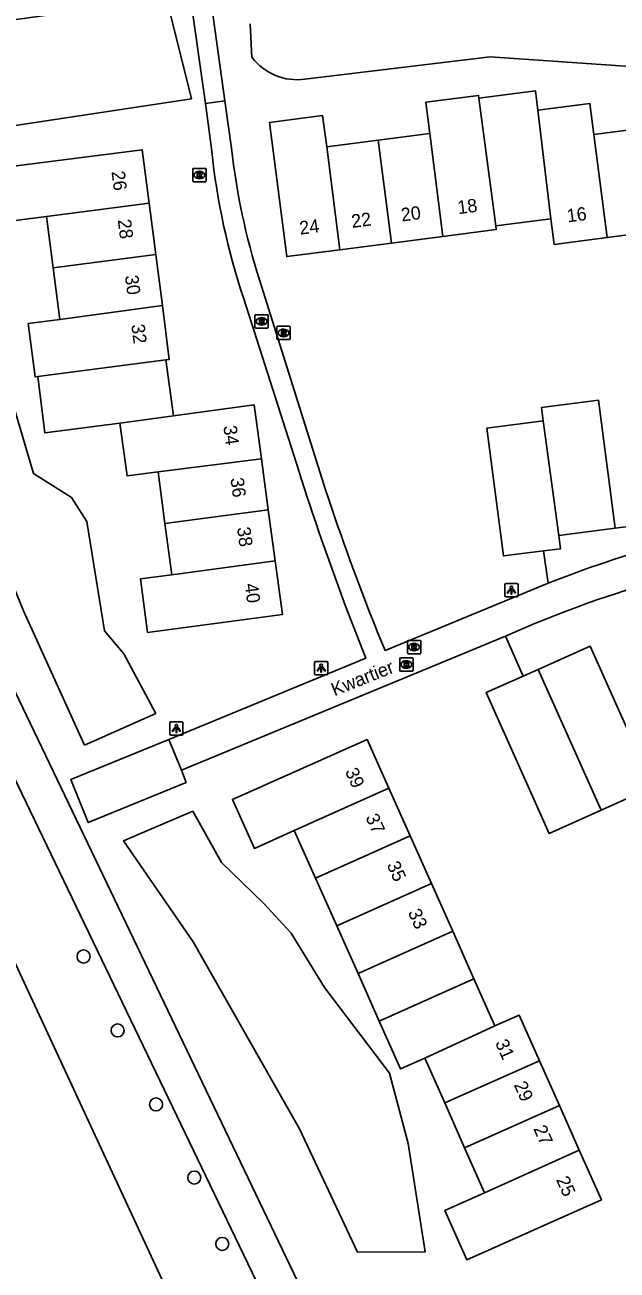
# Model space of a CAD drawing. Extents: x 159451 to 160663, y 388402 to 389723.
# Drawn here: x 159511.2 to 159555.6, y 389199.9 to 389293.3 of the extents above; entities that cross this region are included whole.
import ezdxf

# ---------------------------------------------------------------- set-up
doc = ezdxf.new("R2010")
doc.units = 0
for name, color, linetype in [('IMGEO_Boom', 7, 'Continuous'), ('IMGEO_Bouwland', 7, 'Continuous'), ('IMGEO_Grasland_overig', 7, 'Continuous'), ('IMGEO_Lichtpunt', 7, 'Continuous'), ('IMGEO_Meer_plas_ven_vijver', 7, 'Continuous'), ('IMGEO_Openbare_ruimte_label', 7, 'Continuous'), ('IMGEO_Pand', 7, 'Continuous'), ('IMGEO_Pand_nummerreeks', 7, 'Continuous'), ('IMGEO_Rijbaan_lokaal_gesloten', 7, 'Continuous'), ('IMGEO_Rijbaan_lokaal_halfverhard', 7, 'Continuous'), ('IMGEO_Rioolput', 7, 'Continuous')]:
    doc.layers.add(name, color=color, linetype=linetype)

msp = doc.modelspace()

# ---------------------------------------------------------------- linework, layer by layer
at = {"layer": 'IMGEO_Boom'}
for centre in [(159515.645, 389223.44), (159518.196, 389217.898), (159521.076, 389212.352), (159523.945, 389206.87), (159526.044, 389201.9)]:
    msp.add_circle(centre, 0.489, dxfattribs=at)
at = {"layer": 'IMGEO_Bouwland'}
msp.add_lwpolyline([(159539.156, 389122.203), (159538.081, 389141.023), (159537.243, 389155.693), (159534.303, 389168.702), (159530.224, 389180.456), (159487.441, 389272.575)], dxfattribs=at)
at = {"layer": 'IMGEO_Grasland_overig'}
for points in [[(159552.375, 389144.269), (159550.196, 389160.656), (159546.355, 389164.126), (159540.689, 389183.824), (159539.945, 389186.409), (159538.67, 389189.107), (159536.847, 389188.304), (159486.712, 389292.863)], [(159493.1, 389273.212), (159500, 389258.58), (159504.093, 389250), (159534.245, 389187.399), (159541.062, 389164.374)]]:
    msp.add_lwpolyline(points, dxfattribs=at)
at = {"layer": 'IMGEO_Lichtpunt'}
for p, q in [((159547.227, 389251.307), (159547.227, 389250.5)), ((159547.227, 389251.307), (159547.227, 389250.5)), ((159548.129, 389251.402), (159547.321, 389251.402)), ((159548.129, 389251.402), (159547.321, 389251.402)), ((159548.223, 389250.5), (159548.223, 389251.307)), ((159548.223, 389250.5), (159548.223, 389251.307)), ((159547.321, 389250.406), (159548.129, 389250.406)), ((159547.321, 389250.406), (159548.129, 389250.406)), ((159532.965, 389245.462), (159532.965, 389244.655)), ((159532.965, 389245.462), (159532.965, 389244.655)), ((159533.867, 389245.557), (159533.059, 389245.557)), ((159533.867, 389245.557), (159533.059, 389245.557)), ((159533.961, 389244.655), (159533.961, 389245.462)), ((159533.961, 389244.655), (159533.961, 389245.462)), ((159533.059, 389244.561), (159533.867, 389244.561)), ((159533.059, 389244.561), (159533.867, 389244.561)), ((159522.102, 389240.935), (159522.102, 389240.128)), ((159522.102, 389240.935), (159522.102, 389240.128)), ((159523.004, 389241.03), (159522.196, 389241.03)), ((159523.004, 389241.03), (159522.196, 389241.03)), ((159523.098, 389240.128), (159523.098, 389240.935)), ((159523.098, 389240.128), (159523.098, 389240.935)), ((159522.196, 389240.034), (159523.004, 389240.034)), ((159522.196, 389240.034), (159523.004, 389240.034))]:
    msp.add_line(p, q, dxfattribs=at)
for points in [[(159547.601, 389250.971), (159547.64, 389250.943), (159547.452, 389250.681), (159547.414, 389250.708), (159547.601, 389250.971)], [(159547.703, 389250.923), (159547.75, 389250.923), (159547.75, 389250.601), (159547.703, 389250.601), (159547.703, 389250.923)], [(159547.813, 389250.943), (159547.851, 389250.97), (159548.038, 389250.708), (159547.999, 389250.68), (159547.813, 389250.943)], [(159533.339, 389245.126), (159533.378, 389245.098), (159533.19, 389244.836), (159533.152, 389244.863), (159533.339, 389245.126)], [(159533.441, 389245.078), (159533.488, 389245.078), (159533.488, 389244.756), (159533.441, 389244.756), (159533.441, 389245.078)], [(159533.551, 389245.098), (159533.589, 389245.125), (159533.776, 389244.863), (159533.737, 389244.835), (159533.551, 389245.098)], [(159522.476, 389240.599), (159522.515, 389240.571), (159522.327, 389240.309), (159522.289, 389240.336), (159522.476, 389240.599)], [(159522.578, 389240.551), (159522.625, 389240.551), (159522.625, 389240.229), (159522.578, 389240.229), (159522.578, 389240.551)], [(159522.688, 389240.571), (159522.726, 389240.598), (159522.913, 389240.336), (159522.874, 389240.308), (159522.688, 389240.571)]]:
    msp.add_lwpolyline(points, dxfattribs=at)
for centre in [(159547.726, 389251.105), (159533.464, 389245.26), (159522.601, 389240.733)]:
    msp.add_circle(centre, 0.0994, dxfattribs=at)
for centre, start, end in [((159547.321, 389251.307), 90, 180), ((159547.321, 389251.307), 90, 180), ((159548.129, 389251.307), 0, 90), ((159548.129, 389251.307), 0, 90), ((159547.321, 389250.5), 180, 270), ((159547.321, 389250.5), 180, 270), ((159548.129, 389250.5), 270, 0), ((159548.129, 389250.5), 270, 360), ((159533.059, 389245.462), 90, 180), ((159533.059, 389245.462), 90, 180), ((159533.867, 389245.462), 0, 90), ((159533.867, 389245.462), 0, 90), ((159533.059, 389244.655), 180, 270), ((159533.059, 389244.655), 180, 270), ((159533.867, 389244.655), 270, 0), ((159533.867, 389244.655), 270, 360), ((159522.196, 389240.935), 90, 180), ((159522.196, 389240.935), 90, 180), ((159523.004, 389240.935), 0, 90), ((159523.004, 389240.935), 0, 90), ((159522.196, 389240.128), 180, 270), ((159522.196, 389240.128), 180, 270), ((159523.004, 389240.128), 270, 0), ((159523.004, 389240.128), 270, 360)]:
    msp.add_arc(centre, 0.0946, start, end, dxfattribs=at)
at = {"layer": 'IMGEO_Meer_plas_ven_vijver'}
for points in [[(159521.069, 389241.65), (159518.659, 389246.126), (159517.22, 389247.851), (159515.886, 389256.055), (159514.744, 389257.84), (159511.894, 389259.653), (159504.61, 389284.226), (159509.011, 389285.515), (159523.74, 389287.733), (159521.85, 389295.267), (159496.278, 389291.663), (159494.831, 389290.177), (159494.743, 389289.39), (159511.127, 389249.352), (159515.724, 389239.283), (159521.069, 389241.65)], [(159528.272, 389290.814), (159528.13, 389293.352)], [(159556.966, 389290.126), (159546.129, 389290.863), (159532.239, 389289.197)], [(159523.847, 389234.341), (159518.626, 389232.107), (159523.869, 389224.551), (159531.83, 389210.522), (159536.188, 389201.27), (159541.252, 389201.297), (159539.985, 389209.42), (159538.578, 389214.693), (159533.719, 389221.109), (159531.217, 389225.185), (159529.13, 389227.44), (159525.975, 389230.482), (159523.847, 389234.341)]]:
    msp.add_lwpolyline(points, dxfattribs=at)
msp.add_arc((159531.661, 389293.453), 4.295, 217.90944, 277.73769, dxfattribs=at)
at = {"layer": 'IMGEO_Pand'}
for points in [[(159541.594, 389285.127), (159541.295, 389287.473), (159545.256, 389287.981), (159545.281, 389287.787)], [(159545.281, 389287.787), (159549.518, 389288.329), (159549.707, 389286.878)], [(159546.558, 389278.199), (159545.281, 389287.787)], [(159549.707, 389286.878), (159553.612, 389287.385), (159553.913, 389285.047)], [(159549.707, 389286.878), (159550.68, 389278.733)], [(159534.868, 389276.415), (159530.881, 389275.898), (159529.576, 389285.954), (159533.569, 389286.469), (159533.872, 389284.123)], [(159537.733, 389284.625), (159541.594, 389285.127)], [(159542.577, 389277.414), (159541.594, 389285.127)], [(159553.913, 389285.047), (159557.776, 389285.546)], [(159553.913, 389285.047), (159554.906, 389277.332)], [(159520.557, 389279.914), (159520.041, 389283.908), (159510.008, 389282.625), (159510.521, 389278.616), (159512.856, 389278.918)], [(159533.872, 389284.123), (159537.733, 389284.625)], [(159534.868, 389276.415), (159533.872, 389284.123)], [(159538.735, 389276.916), (159537.733, 389284.625)], [(159520.557, 389279.914), (159512.856, 389278.918)], [(159521.057, 389276.054), (159520.557, 389279.914)], [(159512.856, 389278.918), (159513.355, 389275.058)], [(159546.558, 389278.199), (159546.592, 389277.935), (159542.577, 389277.414)], [(159550.68, 389278.733), (159546.558, 389278.199)], [(159554.906, 389277.332), (159550.926, 389276.815), (159550.68, 389278.733)], [(159542.577, 389277.414), (159538.735, 389276.916)], [(159558.771, 389277.834), (159554.906, 389277.332)], [(159538.735, 389276.916), (159534.868, 389276.415)], [(159513.355, 389275.058), (159521.057, 389276.054)], [(159521.551, 389272.231), (159521.057, 389276.054)], [(159513.355, 389275.058), (159513.854, 389271.198)], [(159521.551, 389272.231), (159513.854, 389271.198)], [(159521.819, 389268.158), (159522.073, 389268.192), (159521.551, 389272.231)], [(159513.854, 389271.198), (159511.491, 389270.881), (159512.009, 389266.885), (159512.202, 389266.91)], [(159512.202, 389266.91), (159521.819, 389268.158)], [(159521.819, 389268.158), (159522.384, 389263.975)], [(159518.374, 389263.415), (159512.749, 389262.686), (159512.202, 389266.91)], [(159550.103, 389263.588), (159549.974, 389264.586), (159554.246, 389265.142), (159555.492, 389255.556)], [(159528.974, 389260.743), (159528.428, 389264.791), (159522.384, 389263.975)], [(159522.384, 389263.975), (159518.374, 389263.415)], [(159518.374, 389263.415), (159518.902, 389259.462), (159521.237, 389259.759)], [(159550.103, 389263.588), (159545.873, 389263.038), (159547.128, 389253.464), (159550.122, 389253.843)], [(159551.271, 389255.006), (159550.103, 389263.588)], [(159528.974, 389260.743), (159521.237, 389259.759)], [(159529.489, 389256.929), (159528.974, 389260.743)], [(159521.237, 389259.759), (159521.746, 389255.905)], [(159529.489, 389256.929), (159521.746, 389255.905)], [(159530.008, 389253.087), (159529.489, 389256.929)], [(159521.746, 389255.905), (159522.256, 389252.051)], [(159550.122, 389253.843), (159551.405, 389254.005), (159551.271, 389255.006)], [(159555.492, 389255.556), (159551.271, 389255.006)], [(159522.256, 389252.051), (159519.913, 389251.738), (159520.446, 389247.737), (159530.55, 389249.068), (159530.008, 389253.087)], [(159522.256, 389252.051), (159530.008, 389253.087)], [(159549.724, 389244.959), (159553.631, 389246.699), (159557.562, 389237.923)], [(159548.614, 389244.465), (159549.724, 389244.959)], [(159554.447, 389234.413), (159549.724, 389244.959)], [(159548.614, 389244.465), (159545.842, 389243.23), (159550.543, 389232.664), (159554.447, 389234.413)], [(159531.434, 389232.875), (159528.453, 389231.539), (159526.807, 389235.21), (159536.903, 389239.704), (159538.532, 389236.056)], [(159554.447, 389234.413), (159558.351, 389236.161), (159557.562, 389237.923)], [(159538.532, 389236.056), (159531.434, 389232.875)], [(159538.532, 389236.056), (159540.13, 389232.476)], [(159533.03, 389229.303), (159531.434, 389232.875)], [(159540.13, 389232.476), (159533.03, 389229.303)], [(159540.13, 389232.476), (159541.724, 389228.904)], [(159534.626, 389225.732), (159533.03, 389229.303)], [(159534.626, 389225.732), (159541.724, 389228.904)], [(159541.724, 389228.904), (159543.319, 389225.331)], [(159536.221, 389222.16), (159534.626, 389225.732)], [(159543.319, 389225.331), (159536.221, 389222.16)], [(159543.319, 389225.331), (159544.914, 389221.759)], [(159537.817, 389218.589), (159536.221, 389222.16)], [(159537.817, 389218.589), (159544.914, 389221.759)], [(159544.914, 389221.759), (159546.482, 389218.246)], [(159541.221, 389215.825), (159539.413, 389215.017), (159537.817, 389218.589)], [(159546.482, 389218.246), (159548.293, 389219.053), (159549.821, 389215.625)], [(159546.482, 389218.246), (159541.221, 389215.825)], [(159542.719, 389212.462), (159541.221, 389215.825)], [(159542.719, 389212.462), (159549.821, 389215.625)], [(159549.821, 389215.625), (159551.319, 389212.262)], [(159544.217, 389209.098), (159542.719, 389212.462)], [(159544.217, 389209.098), (159551.319, 389212.262)], [(159551.319, 389212.262), (159552.806, 389208.926)], [(159545.715, 389205.735), (159544.217, 389209.098)], [(159552.806, 389208.926), (159554.466, 389205.201), (159544.38, 389200.71), (159542.733, 389204.393), (159545.715, 389205.735)], [(159545.715, 389205.735), (159552.806, 389208.926)]]:
    msp.add_lwpolyline(points, dxfattribs=at)
at = {"layer": 'IMGEO_Rijbaan_lokaal_gesloten'}
for points in [[(159523.669, 389295.299), (159524.796, 389287.372)], [(159526.226, 389287.573), (159525.136, 389295.518)], [(159524.796, 389287.372), (159526.226, 389287.573)], [(159526.723, 389284.029), (159526.226, 389287.573)], [(159524.796, 389287.372), (159525.256, 389283.811)], [(159533.776, 389258.43), (159528.825, 389274.169)], [(159527.637, 389272.799), (159531.804, 389259.756)], [(159550.467, 389251.425), (159538.251, 389246.377), (159537.657, 389247.809)], [(159535.285, 389249.699), (159536.816, 389245.805), (159522.027, 389239.718)], [(159522.997, 389237.416), (159547.283, 389247.447)], [(159522.027, 389239.718), (159514.682, 389236.714), (159515.988, 389233.475), (159523.334, 389236.494), (159522.997, 389237.416)], [(159522.997, 389237.416), (159522.027, 389239.718)]]:
    msp.add_lwpolyline(points, dxfattribs=at)
for centre, radius, start, end in [((159576.84, 389289.201), 51.865, 185.96525, 198.43596), ((159579.613, 389290.15), 53.243, 186.60177, 197.46708), ((159748.156, 389329.01), 227.166, 197.74989, 200.43436), ((159718.88, 389320.049), 195.091, 198.41199, 201.73344), ((159584.912, 389163.233), 94.68, 105.81014, 111.33379), ((159582.261, 389169.306), 85.612, 105.35087, 114.11468)]:
    msp.add_arc(centre, radius, start, end, dxfattribs=at)
at = {"layer": 'IMGEO_Rijbaan_lokaal_halfverhard'}
for points in [[(159555.492, 389255.556), (159558.754, 389255.947), (159559.116, 389254.331)], [(159550.467, 389251.425), (159550.122, 389253.843)], [(159547.283, 389247.447), (159548.614, 389244.465)]]:
    msp.add_lwpolyline(points, dxfattribs=at)
at = {"layer": 'IMGEO_Rioolput'}
for p, q in [((159523.83, 389281.589), (159523.83, 389282.441)), ((159523.905, 389282.515), (159524.757, 389282.515)), ((159524.318, 389282.295), (159524.343, 389282.295)), ((159524.831, 389282.441), (159524.831, 389281.589)), ((159524.757, 389281.515), (159523.905, 389281.515)), ((159524.341, 389281.735), (159524.316, 389281.735)), ((159528.494, 389270.621), (159528.494, 389271.473)), ((159528.569, 389271.547), (159529.421, 389271.547)), ((159529.005, 389270.767), (159528.98, 389270.767)), ((159528.982, 389271.327), (159529.007, 389271.327)), ((159529.495, 389271.473), (159529.495, 389270.621)), ((159530.212, 389270.679), (159531.064, 389270.679)), ((159529.421, 389270.547), (159528.569, 389270.547)), ((159530.137, 389269.753), (159530.137, 389270.605)), ((159530.648, 389269.899), (159530.623, 389269.899)), ((159530.625, 389270.459), (159530.65, 389270.459)), ((159531.138, 389270.605), (159531.138, 389269.753)), ((159531.064, 389269.679), (159530.212, 389269.679)), ((159539.923, 389246.21), (159539.923, 389247.062)), ((159539.998, 389247.136), (159540.85, 389247.136)), ((159540.411, 389246.916), (159540.436, 389246.916)), ((159540.924, 389247.062), (159540.924, 389246.21)), ((159539.345, 389244.902), (159539.345, 389245.754)), ((159539.42, 389245.828), (159540.272, 389245.828)), ((159539.833, 389245.608), (159539.858, 389245.608)), ((159540.85, 389246.136), (159539.998, 389246.136)), ((159540.346, 389245.754), (159540.346, 389244.902)), ((159540.434, 389246.356), (159540.409, 389246.356)), ((159540.272, 389244.828), (159539.42, 389244.828)), ((159539.856, 389245.048), (159539.831, 389245.048))]:
    msp.add_line(p, q, dxfattribs=at)
for points in [[(159523.83, 389281.589), (159523.83, 389282.441)], [(159523.905, 389282.515), (159524.757, 389282.515)], [(159524.419, 389282.213), (159524.167, 389282.215), (159524.167, 389281.815)], [(159524.167, 389281.815), (159524.291, 389281.815), (159524.291, 389281.977), (159524.302, 389281.977)], [(159524.345, 389282.134), (159524.291, 389282.134), (159524.291, 389282.053)], [(159524.291, 389282.053), (159524.343, 389282.053)], [(159524.349, 389281.948), (159524.42, 389281.815), (159524.56, 389281.815), (159524.495, 389281.941)], [(159524.831, 389282.441), (159524.831, 389281.589)], [(159524.757, 389281.515), (159523.905, 389281.515)], [(159528.494, 389270.621), (159528.494, 389271.473)], [(159528.569, 389271.547), (159529.421, 389271.547)], [(159529.083, 389271.245), (159528.831, 389271.247), (159528.831, 389270.847)], [(159528.831, 389270.847), (159528.955, 389270.847), (159528.955, 389271.009), (159528.966, 389271.009)], [(159529.009, 389271.166), (159528.955, 389271.166), (159528.955, 389271.085)], [(159528.955, 389271.085), (159529.007, 389271.085)], [(159529.013, 389270.98), (159529.084, 389270.847), (159529.224, 389270.847), (159529.159, 389270.973)], [(159529.495, 389271.473), (159529.495, 389270.621)], [(159530.212, 389270.679), (159531.064, 389270.679)], [(159529.421, 389270.547), (159528.569, 389270.547)], [(159530.137, 389269.753), (159530.137, 389270.605)], [(159530.726, 389270.377), (159530.474, 389270.379), (159530.474, 389269.979)], [(159530.474, 389269.979), (159530.598, 389269.979), (159530.598, 389270.141), (159530.609, 389270.141)], [(159530.652, 389270.298), (159530.598, 389270.298), (159530.598, 389270.217)], [(159530.598, 389270.217), (159530.65, 389270.217)], [(159530.656, 389270.112), (159530.727, 389269.979), (159530.867, 389269.979), (159530.802, 389270.105)], [(159531.138, 389270.605), (159531.138, 389269.753)], [(159531.064, 389269.679), (159530.212, 389269.679)], [(159539.923, 389246.21), (159539.923, 389247.062)], [(159539.998, 389247.136), (159540.85, 389247.136)], [(159540.512, 389246.834), (159540.26, 389246.836), (159540.26, 389246.436)], [(159540.26, 389246.436), (159540.384, 389246.436), (159540.384, 389246.598), (159540.395, 389246.598)], [(159540.438, 389246.755), (159540.384, 389246.755), (159540.384, 389246.674)], [(159540.384, 389246.674), (159540.436, 389246.674)], [(159540.442, 389246.569), (159540.513, 389246.436), (159540.653, 389246.436), (159540.588, 389246.562)], [(159540.924, 389247.062), (159540.924, 389246.21)], [(159539.345, 389244.902), (159539.345, 389245.754)], [(159539.42, 389245.828), (159540.272, 389245.828)], [(159539.934, 389245.526), (159539.682, 389245.528), (159539.682, 389245.128)], [(159540.85, 389246.136), (159539.998, 389246.136)], [(159540.346, 389245.754), (159540.346, 389244.902)], [(159540.272, 389244.828), (159539.42, 389244.828)], [(159539.682, 389245.128), (159539.806, 389245.128), (159539.806, 389245.29), (159539.817, 389245.29)], [(159539.86, 389245.447), (159539.806, 389245.447), (159539.806, 389245.366)], [(159539.806, 389245.366), (159539.858, 389245.366)], [(159539.864, 389245.261), (159539.935, 389245.128), (159540.075, 389245.128), (159540.01, 389245.254)]]:
    msp.add_lwpolyline(points, dxfattribs=at)
for centre, radius, start, end in [((159523.907, 389282.439), 0.0765, 91.55205, 178.44795), ((159523.907, 389282.439), 0.0765, 91.55205, 178.44795), ((159524.301, 389281.924), 0.0533, 26.02933, 88.69889), ((159524.327, 389282.242), 0.19, 274.7715, 282.96867), ((159524.351, 389282.038), 0.0964, 77.00612, 93.18647), ((159524.365, 389282.095), 0.0378, 276.66336, 79.67722), ((159524.418, 389282.103), 0.109, 350.36119, 89.41601), ((159524.416, 389282.103), 0.112, 277.58423, 350.98172), ((159524.4, 389281.888), 0.108, 29.51342, 73.79051), ((159524.755, 389282.439), 0.0765, 1.55205, 88.44795), ((159524.755, 389282.439), 0.0765, 1.55205, 88.44795), ((159523.907, 389281.591), 0.0765, 181.55205, 268.44795), ((159523.907, 389281.591), 0.0765, 181.55205, 268.44795), ((159524.755, 389281.591), 0.0765, 271.55205, 358.44795), ((159524.755, 389281.591), 0.0765, 271.55205, 358.44795), ((159528.571, 389271.471), 0.0765, 91.55205, 178.44795), ((159528.571, 389271.471), 0.0765, 91.55205, 178.44795), ((159528.965, 389270.956), 0.0533, 26.02933, 88.69889), ((159528.991, 389271.274), 0.19, 274.7715, 282.96867), ((159529.015, 389271.07), 0.0964, 77.00612, 93.18647), ((159529.029, 389271.127), 0.0378, 276.66336, 79.67722), ((159529.082, 389271.135), 0.109, 350.36119, 89.41601), ((159529.08, 389271.135), 0.112, 277.58423, 350.98172), ((159529.064, 389270.92), 0.108, 29.51342, 73.79051), ((159529.419, 389271.471), 0.0765, 1.55205, 88.44795), ((159529.419, 389271.471), 0.0765, 1.55205, 88.44795), ((159530.214, 389270.603), 0.0765, 91.55205, 178.44795), ((159530.214, 389270.603), 0.0765, 91.55205, 178.44795), ((159531.062, 389270.603), 0.0765, 1.55205, 88.44795), ((159531.062, 389270.603), 0.0765, 1.55205, 88.44795), ((159528.571, 389270.623), 0.0765, 181.55205, 268.44795), ((159528.571, 389270.623), 0.0765, 181.55205, 268.44795), ((159529.419, 389270.623), 0.0765, 271.55205, 358.44795), ((159529.419, 389270.623), 0.0765, 271.55205, 358.44795), ((159530.214, 389269.755), 0.0765, 181.55205, 268.44795), ((159530.214, 389269.755), 0.0765, 181.55205, 268.44795), ((159530.608, 389270.088), 0.0533, 26.02933, 88.69889), ((159530.634, 389270.406), 0.19, 274.7715, 282.96867), ((159530.658, 389270.202), 0.0964, 77.00612, 93.18647), ((159530.672, 389270.259), 0.0378, 276.66336, 79.67722), ((159530.725, 389270.267), 0.109, 350.36119, 89.41601), ((159530.723, 389270.267), 0.112, 277.58423, 350.98172), ((159530.707, 389270.052), 0.108, 29.51342, 73.79051), ((159531.062, 389269.755), 0.0765, 271.55205, 358.44795), ((159531.062, 389269.755), 0.0765, 271.55205, 358.44795), ((159540, 389247.06), 0.0765, 91.55205, 178.44795), ((159540, 389247.06), 0.0765, 91.55205, 178.44795), ((159540.394, 389246.545), 0.0533, 26.02933, 88.69889), ((159540.42, 389246.863), 0.19, 274.7715, 282.96867), ((159540.444, 389246.659), 0.0964, 77.00612, 93.18647), ((159540.458, 389246.716), 0.0378, 276.66336, 79.67722), ((159540.511, 389246.724), 0.109, 350.36119, 89.41601), ((159540.509, 389246.724), 0.112, 277.58423, 350.98172), ((159540.493, 389246.509), 0.108, 29.51342, 73.79051), ((159540.848, 389247.06), 0.0765, 1.55205, 88.44795), ((159540.848, 389247.06), 0.0765, 1.55205, 88.44795), ((159539.422, 389245.752), 0.0765, 91.55205, 178.44795), ((159539.422, 389245.752), 0.0765, 91.55205, 178.44795), ((159540, 389246.212), 0.0765, 181.55205, 268.44795), ((159540, 389246.212), 0.0765, 181.55205, 268.44795), ((159539.933, 389245.416), 0.109, 350.36119, 89.41601), ((159540.27, 389245.752), 0.0765, 1.55205, 88.44795), ((159540.27, 389245.752), 0.0765, 1.55205, 88.44795), ((159540.848, 389246.212), 0.0765, 271.55205, 358.44795), ((159540.848, 389246.212), 0.0765, 271.55205, 358.44795), ((159539.422, 389244.904), 0.0765, 181.55205, 268.44795), ((159539.422, 389244.904), 0.0765, 181.55205, 268.44795), ((159539.816, 389245.237), 0.0533, 26.02933, 88.69889), ((159539.842, 389245.555), 0.19, 274.7715, 282.96867), ((159539.866, 389245.351), 0.0964, 77.00612, 93.18647), ((159539.88, 389245.408), 0.0378, 276.66336, 79.67722), ((159539.931, 389245.416), 0.112, 277.58423, 350.98172), ((159539.915, 389245.201), 0.108, 29.51342, 73.79051), ((159540.27, 389244.904), 0.0765, 271.55205, 358.44795), ((159540.27, 389244.904), 0.0765, 271.55205, 358.44795)]:
    msp.add_arc(centre, radius, start, end, dxfattribs=at)
for centre, major_axis, ratio, start_param, end_param in [((159524.317, 389282.015), (-0.387, 0.002), 0.722429, 4.712389, 7.853982), ((159524.342, 389282.015), (-0.39, 0.002), 0.717154, 1.570796, 4.712389), ((159528.981, 389271.047), (-0.387, 0.002), 0.722429, 4.712389, 7.853982), ((159529.006, 389271.047), (-0.39, 0.002), 0.717154, 1.570796, 4.712389), ((159530.624, 389270.179), (-0.387, 0.002), 0.722429, 4.712389, 7.853982), ((159530.649, 389270.179), (-0.39, 0.002), 0.717154, 1.570796, 4.712389), ((159540.41, 389246.636), (-0.387, 0.002), 0.722429, 4.712389, 7.853982), ((159540.435, 389246.636), (-0.39, 0.002), 0.717154, 1.570796, 4.712389), ((159539.832, 389245.328), (-0.387, 0.002), 0.722429, 4.712389, 7.853982), ((159539.857, 389245.328), (-0.39, 0.002), 0.717154, 1.570796, 4.712389)]:
    msp.add_ellipse(centre, major_axis=major_axis, ratio=ratio, start_param=start_param, end_param=end_param, dxfattribs=at)

# ---------------------------------------------------------------- texts
at = {"layer": 'IMGEO_Openbare_ruimte_label'}
msp.add_text('Kwartier', height=1, rotation=21.71629, dxfattribs=at).set_placement((159534.454, 389242.938))
at = {"layer": 'IMGEO_Pand_nummerreeks'}
for s, rotation, p in [('26', 277.36803, (159517.732, 389282.268)), ('18', 7.38543, (159543.744, 389279.078)), ('22', 7.38543, (159535.789, 389278.047)), ('20', 7.38543, (159539.508, 389278.529)), ('16', 7.40261, (159551.942, 389278.46)), ('28', 277.36803, (159518.201, 389278.644)), ('24', 7.38543, (159531.892, 389277.542)), ('30', 277.36803, (159518.742, 389274.455)), ('32', 277.36803, (159519.216, 389270.788)), ('34', 277.68888, (159526.122, 389263.187)), ('36', 277.68888, (159526.65, 389259.271)), ('38', 277.68888, (159527.149, 389255.576)), ('40', 277.68888, (159527.719, 389251.351)), ('39', 294.05829, (159535.229, 389237.321)), ('37', 294.05829, (159536.766, 389233.879)), ('35', 294.05829, (159538.358, 389230.313)), ('33', 294.05829, (159539.946, 389226.755)), ('31', 294.01818, (159546.484, 389216.971)), ('29', 294.01818, (159547.886, 389213.825)), ('27', 294.01818, (159549.35, 389210.54)), ('25', 294.01818, (159551.058, 389206.707))]:
    msp.add_text(s, height=1, rotation=rotation, dxfattribs=at).set_placement(p)

doc.saveas('drawing.dxf')
